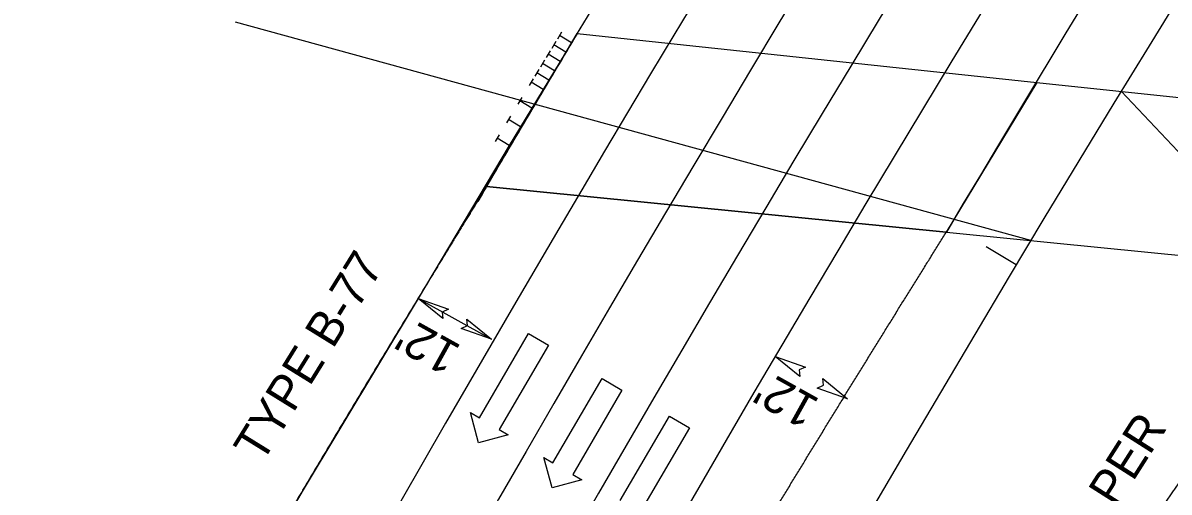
# Model space of a CAD drawing. Extents: x 2389694 to 2405615, y 546931 to 573532.
# Drawn here: x 2395584.9 to 2395749, y 557246.1 to 557313.3 of the extents above; entities that cross this region are included whole.
import ezdxf

# ---------------------------------------------------------------- set-up
doc = ezdxf.new("R2010")
doc.units = 0
for name, color, linetype in [('Prop Approach Slab', 7, 'Continuous'), ('Prop Approach Slab Hatching', 7, 'Continuous'), ('Prop Dimension', 7, 'Continuous'), ('Prop Dimension Text', 7, 'Continuous'), ('Prop EOT', 7, 'Continuous'), ('Prop Guardrail', 7, 'Continuous'), ('Prop Horizontal Alignment', 7, 'Continuous'), ('Prop Horizontal Alignment Tick Small', 7, 'Continuous'), ('Prop Lane Arrow Through CELL', 7, 'Continuous'), ('Prop Lane Lines', 7, 'Continuous'), ('Prop SAU III Approach CELL', 7, 'Continuous')]:
    doc.layers.add(name, color=color, linetype=linetype)

msp = doc.modelspace()

# ---------------------------------------------------------------- linework, layer by layer
at = {"layer": 'Prop Approach Slab'}
msp.add_line((2395664.25, 557311.81), (2395730.1, 557304.82), dxfattribs=at)
for centre, radius, start, end in [((2398729.82, 555480.32), 3571, 139.17799, 149.55348), ((2398605.53, 555570.18), 3358.23, 138.93949, 149.32692)]:
    msp.add_arc(centre, radius, start, end, dxfattribs=at)
at = {"layer": 'Prop Approach Slab Hatching'}
msp.add_line((2395651.25, 557289.87), (2395717.14, 557283.35), dxfattribs=at)
msp.add_lwpolyline([(2395651.25, 557289.87), (2395656.75, 557299.18), (2395664.25, 557311.81), (2395730.1, 557304.82), (2395717.14, 557283.35), (2395717.14, 557283.35)], close=True, dxfattribs=at)
msp.add_arc((2398729.82, 555480.32), 3571, 149.16386, 149.57311, dxfattribs=at)
at = {"layer": 'Prop Dimension'}
for p, q in [((2395729.25, 557282.15), (2395615.3, 557313.46)), ((2395730.1, 557304.82), (2395782.96, 557299.21)), ((2395742.2, 557303.54), (2395817.06, 557224.11)), ((2395651.25, 557289.87), (2395820.89, 557273.08)), ((2395641.5, 557273.85), (2395651.99, 557268.01))]:
    msp.add_line(p, q, dxfattribs=at)
for points in [[(2395645.04, 557270.96), (2395641.5, 557273.85), (2395645.84, 557272.31), (2395644.94, 557271.9)], [(2395648.45, 557270.9), (2395651.99, 557268.01), (2395647.65, 557269.54), (2395648.55, 557269.95)], [(2395696.16, 557262.66), (2395692.62, 557265.55), (2395696.95, 557264.02), (2395696.06, 557263.6)], [(2395699.44, 557262.36), (2395702.98, 557259.46), (2395698.65, 557261), (2395699.54, 557261.41)]]:
    msp.add_lwpolyline(points, close=True, dxfattribs=at)
at = {"layer": 'Prop EOT'}
msp.add_line((2395650.63, 557288.81), (2395650.01, 557287.76), dxfattribs=at)
for radius, end in [(3559, 163.17888), (3523, 169.40696), (3453, 155.44499), (3429, 155.44499)]:
    msp.add_arc((2398729.82, 555480.32), radius, 136.54853, end, dxfattribs=at)
for points in [[(2395651.25, 557289.87), (2395650.89, 557289.28), (2395650.53, 557288.69), (2395650.17, 557288.1), (2395649.81, 557287.52), (2395649.45, 557286.93), (2395649.09, 557286.34), (2395648.73, 557285.75), (2395648.36, 557285.16), (2395648.01, 557284.58), (2395647.65, 557283.99), (2395647.29, 557283.4), (2395646.93, 557282.81), (2395646.57, 557282.23), (2395646.21, 557281.64), (2395645.85, 557281.04), (2395645.49, 557280.46), (2395645.13, 557279.87), (2395644.77, 557279.28), (2395644.41, 557278.69), (2395644.06, 557278.11), (2395643.7, 557277.51), (2395643.34, 557276.93), (2395642.98, 557276.34), (2395642.62, 557275.74), (2395642.26, 557275.16), (2395641.9, 557274.57), (2395641.55, 557273.98), (2395641.19, 557273.39), (2395640.83, 557272.8), (2395640.47, 557272.21), (2395640.11, 557271.62), (2395639.76, 557271.03), (2395639.4, 557270.44), (2395639.04, 557269.85), (2395638.68, 557269.26), (2395638.33, 557268.68), (2395637.97, 557268.08), (2395637.61, 557267.49), (2395637.26, 557266.9), (2395636.9, 557266.31), (2395636.55, 557265.72), (2395636.19, 557265.13), (2395635.83, 557264.54), (2395635.48, 557263.95), (2395635.12, 557263.35), (2395634.77, 557262.77), (2395634.41, 557262.17), (2395634.05, 557261.59), (2395633.7, 557260.99), (2395633.34, 557260.41), (2395632.99, 557259.81), (2395632.63, 557259.22), (2395632.28, 557258.63), (2395631.92, 557258.04), (2395631.57, 557257.45), (2395631.21, 557256.85), (2395630.86, 557256.27), (2395630.5, 557255.67), (2395630.15, 557255.09), (2395629.79, 557254.49), (2395629.44, 557253.9), (2395629.09, 557253.31), (2395628.73, 557252.71), (2395628.38, 557252.13), (2395628.02, 557251.53), (2395627.67, 557250.94), (2395627.32, 557250.35), (2395626.96, 557249.75), (2395626.61, 557249.16), (2395626.26, 557248.57), (2395625.91, 557247.98), (2395625.55, 557247.38), (2395625.2, 557246.8), (2395624.85, 557246.2)], [(2395682.12, 557226.17), (2395682.58, 557226.95), (2395683.05, 557227.73), (2395683.52, 557228.5), (2395683.98, 557229.28), (2395684.45, 557230.06), (2395684.92, 557230.83), (2395685.38, 557231.61), (2395685.85, 557232.39), (2395686.32, 557233.16), (2395686.79, 557233.94), (2395687.26, 557234.71), (2395687.72, 557235.49), (2395688.19, 557236.27), (2395688.66, 557237.04), (2395689.13, 557237.82), (2395689.6, 557238.59), (2395690.07, 557239.37), (2395690.54, 557240.14), (2395691.01, 557240.92), (2395691.48, 557241.69), (2395691.95, 557242.47), (2395692.42, 557243.24), (2395692.89, 557244.02), (2395693.36, 557244.79), (2395693.83, 557245.56), (2395694.3, 557246.34), (2395694.77, 557247.11), (2395695.24, 557247.89), (2395695.72, 557248.66), (2395696.19, 557249.43), (2395696.66, 557250.21), (2395697.13, 557250.98), (2395697.6, 557251.75), (2395698.08, 557252.53), (2395698.55, 557253.3), (2395699.02, 557254.07), (2395699.5, 557254.85), (2395699.97, 557255.62), (2395700.44, 557256.39), (2395700.92, 557257.16), (2395701.39, 557257.93), (2395701.86, 557258.71), (2395702.34, 557259.48), (2395702.81, 557260.25), (2395703.29, 557261.02), (2395703.76, 557261.79), (2395704.24, 557262.57), (2395704.71, 557263.34), (2395705.19, 557264.11), (2395705.66, 557264.88), (2395706.14, 557265.65), (2395706.62, 557266.42), (2395707.09, 557267.19), (2395707.57, 557267.96), (2395708.05, 557268.73), (2395708.52, 557269.5), (2395709, 557270.27), (2395709.48, 557271.04), (2395709.96, 557271.81), (2395710.43, 557272.58), (2395710.91, 557273.35), (2395711.39, 557274.12), (2395711.87, 557274.89), (2395712.35, 557275.66), (2395712.83, 557276.43), (2395713.3, 557277.2), (2395713.78, 557277.97), (2395714.26, 557278.74), (2395714.74, 557279.5), (2395715.22, 557280.27), (2395715.7, 557281.04), (2395716.18, 557281.81), (2395717.14, 557283.35)], [(2395759.96, 557261.18), (2395759.56, 557260.61), (2395759.16, 557260.03), (2395758.76, 557259.46), (2395758.36, 557258.88), (2395757.96, 557258.31), (2395757.57, 557257.74), (2395757.17, 557257.17), (2395756.77, 557256.59), (2395756.38, 557256.02), (2395755.98, 557255.45), (2395755.58, 557254.87), (2395755.18, 557254.3), (2395754.79, 557253.72), (2395754.39, 557253.15), (2395753.99, 557252.57), (2395753.6, 557252), (2395753.2, 557251.42), (2395752.8, 557250.85), (2395752.41, 557250.28), (2395752.01, 557249.7), (2395751.61, 557249.13), (2395751.22, 557248.56), (2395750.82, 557247.98), (2395750.43, 557247.4), (2395750.03, 557246.82), (2395749.64, 557246.25), (2395749.24, 557245.68), (2395748.84, 557245.1), (2395748.45, 557244.53), (2395748.06, 557243.95), (2395747.66, 557243.37), (2395747.27, 557242.8), (2395746.87, 557242.22), (2395746.47, 557241.65), (2395746.08, 557241.07), (2395745.68, 557240.49), (2395745.29, 557239.92), (2395744.9, 557239.34), (2395744.5, 557238.76), (2395744.11, 557238.19), (2395743.71, 557237.61), (2395743.32, 557237.04), (2395742.93, 557236.46), (2395742.53, 557235.88), (2395742.14, 557235.31), (2395741.75, 557234.72), (2395741.35, 557234.15), (2395740.96, 557233.58), (2395740.57, 557232.99), (2395740.18, 557232.42), (2395739.78, 557231.84), (2395739.39, 557231.26), (2395739, 557230.69), (2395738.6, 557230.1), (2395738.21, 557229.53), (2395737.82, 557228.96), (2395737.43, 557228.37), (2395737.04, 557227.8), (2395736.64, 557227.21), (2395736.25, 557226.64), (2395735.86, 557226.06), (2395735.47, 557225.48), (2395735.08, 557224.9), (2395734.68, 557224.32), (2395734.3, 557223.74), (2395733.91, 557223.17), (2395733.51, 557222.59), (2395733.12, 557222.01), (2395732.73, 557221.43), (2395732.34, 557220.85), (2395731.95, 557220.27), (2395731.56, 557219.69), (2395731.17, 557219.11), (2395730.78, 557218.54)], [(2395624.85, 557246.2), (2395624.49, 557245.6), (2395624.14, 557245.01), (2395623.79, 557244.42), (2395623.44, 557243.83), (2395623.08, 557243.23), (2395622.73, 557242.65), (2395622.38, 557242.05), (2395622.03, 557241.45), (2395621.68, 557240.86), (2395621.32, 557240.27), (2395620.98, 557239.68), (2395620.62, 557239.08), (2395620.27, 557238.49), (2395619.92, 557237.89), (2395619.57, 557237.3), (2395619.22, 557236.71), (2395618.87, 557236.11), (2395618.52, 557235.52), (2395618.17, 557234.92), (2395617.82, 557234.33), (2395617.47, 557233.74), (2395617.12, 557233.15), (2395616.77, 557232.55), (2395616.41, 557231.95), (2395616.07, 557231.36), (2395615.71, 557230.76), (2395615.37, 557230.17), (2395615.02, 557229.57), (2395614.67, 557228.98), (2395614.32, 557228.39), (2395613.97, 557227.79), (2395613.62, 557227.2), (2395613.27, 557226.6), (2395612.92, 557226.01), (2395612.57, 557225.41), (2395612.23, 557224.82), (2395611.88, 557224.22), (2395611.53, 557223.62), (2395611.18, 557223.03), (2395610.83, 557222.43), (2395610.48, 557221.84), (2395610.13, 557221.24), (2395609.79, 557220.65), (2395609.44, 557220.05), (2395609.09, 557219.45), (2395608.75, 557218.86), (2395608.4, 557218.26), (2395608.05, 557217.67), (2395607.7, 557217.07), (2395607.36, 557216.48), (2395607.01, 557215.88), (2395606.66, 557215.28), (2395606.32, 557214.69), (2395605.97, 557214.09), (2395605.62, 557213.49), (2395605.27, 557212.89), (2395604.93, 557212.3), (2395604.58, 557211.7), (2395604.24, 557211.11), (2395603.89, 557210.51), (2395603.54, 557209.91), (2395603.2, 557209.32), (2395602.85, 557208.72), (2395602.51, 557208.12), (2395602.16, 557207.52), (2395601.82, 557206.93), (2395601.47, 557206.33), (2395601.13, 557205.73), (2395600.78, 557205.14), (2395600.44, 557204.53), (2395600.1, 557203.94), (2395599.75, 557203.34), (2395599.06, 557202.15)]]:
    msp.add_spline(points, degree=3, dxfattribs=at)
at = {"layer": 'Prop Guardrail'}
for p, q in [((2395654.51, 557295.79), (2395641.5, 557273.85)), ((2395641.5, 557273.85), (2395624.85, 557246.2)), ((2395624.85, 557246.2), (2395591.05, 557187.49))]:
    msp.add_line(p, q, dxfattribs=at)
at = {"layer": 'Prop Horizontal Alignment'}
msp.add_arc((2398729.82, 555480.32), 3500, 136.54853, 177.15578, dxfattribs=at)
at = {"layer": 'Prop Horizontal Alignment Tick Small'}
msp.add_line((2395727.16, 557278.66), (2395722.87, 557281.23), dxfattribs=at)
at = {"layer": 'Prop Lane Arrow Through CELL'}
for p, q in [((2395650.25, 557256.72), (2395657.3, 557268.82)), ((2395657.3, 557268.82), (2395660.15, 557267.16)), ((2395660.15, 557267.16), (2395653.1, 557255.06)), ((2395660.78, 557250.27), (2395667.83, 557262.37)), ((2395667.83, 557262.37), (2395670.68, 557260.71)), ((2395670.68, 557260.71), (2395663.63, 557248.61)), ((2395650.13, 557253.14), (2395648.96, 557257.48)), ((2395648.96, 557257.48), (2395650.25, 557256.72)), ((2395670.43, 557244.88), (2395677.48, 557256.97)), ((2395677.48, 557256.97), (2395680.33, 557255.31)), ((2395680.33, 557255.31), (2395673.28, 557243.22)), ((2395654.4, 557254.31), (2395650.13, 557253.14)), ((2395653.1, 557255.06), (2395654.4, 557254.31)), ((2395660.67, 557246.69), (2395659.49, 557251.03)), ((2395659.49, 557251.03), (2395660.78, 557250.27)), ((2395664.93, 557247.85), (2395660.67, 557246.69)), ((2395663.63, 557248.61), (2395664.93, 557247.85))]:
    msp.add_line(p, q, dxfattribs=at)
at = {"layer": 'Prop Lane Lines'}
for radius, end in [(3547, 169.40696), (3535, 169.40696), (3441, 155.44499)]:
    msp.add_arc((2398729.82, 555480.32), radius, 136.54853, end, dxfattribs=at)
at = {"layer": 'Prop SAU III Approach CELL'}
for p, q in [((2395664.25, 557311.81), (2395654.51, 557295.79)), ((2395662.03, 557312), (2395661.44, 557311.03)), ((2395663.44, 557310.48), (2395661.73, 557311.52)), ((2395661.22, 557310.67), (2395660.62, 557309.69)), ((2395662.63, 557309.14), (2395660.92, 557310.18)), ((2395659.6, 557308), (2395659, 557307.02)), ((2395660.41, 557309.34), (2395659.81, 557308.36)), ((2395661.82, 557307.81), (2395660.11, 557308.85)), ((2395658.78, 557306.67), (2395658.19, 557305.69)), ((2395661.01, 557306.47), (2395659.3, 557307.51)), ((2395657.97, 557305.33), (2395657.38, 557304.35)), ((2395659.38, 557303.8), (2395657.67, 557304.84)), ((2395660.19, 557305.14), (2395658.49, 557306.18)), ((2395656.35, 557302.66), (2395655.75, 557301.68)), ((2395657.76, 557301.13), (2395656.05, 557302.17)), ((2395654.72, 557299.99), (2395654.13, 557299.01)), ((2395656.13, 557298.46), (2395654.42, 557299.5)), ((2395653.1, 557297.32), (2395652.5, 557296.34)), ((2395654.51, 557295.79), (2395652.8, 557296.83))]:
    msp.add_line(p, q, dxfattribs=at)

# ---------------------------------------------------------------- texts
at = {"layer": 'Prop Dimension Text'}
for s, rotation, p in [('TYPE B-77', 58.2487, (2395619.09, 557250.06)), ("12'", 150.9193, (2395647.86, 557266.98)), ("12'", 150.9193, (2395699.2, 557259.31)), ('15:1 TAPER', 57.531, (2395728.9, 557223.97))]:
    msp.add_text(s, height=5, rotation=rotation, dxfattribs=at).set_placement(p)

doc.saveas('drawing.dxf')
